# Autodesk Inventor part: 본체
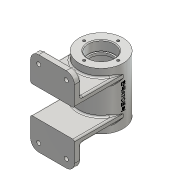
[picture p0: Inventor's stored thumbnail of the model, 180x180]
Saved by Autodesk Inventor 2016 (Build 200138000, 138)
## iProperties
Created: 2017-02
Part Number: 본체
Material: 알루미늄 6061
Document SubType Name: Modeling
Designer: H
Density: 2.7 g/cm^3
Appearance: 알루미늄 - 평지
Mass: 354.768 g
Surface Area: 422.772 cm^2
Volume: 131.396 cm^3
Author: H
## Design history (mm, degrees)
sketch "스케치1"
  geometry: L1 (0, 87.092)-(0, -86.113); L2 (0, 35)-(27, 35); L3 (27, 35)-(27, -35); L4 (27, -35)-(0, -35); L5 (39.632, 10)-(-25.443, 10); L6 (20, 10)-(20, 15); L7 (20, 15)-(32, 15); L8 (32, 15)-(32, 10); 1 further point
  constraints: 16 end point, 5 point on line, 3 perpendicular, 3 vertical, 2 horizontal
  dimensions: "d0" = 35 distance from line of point (0, 0) L2; "d1" = 70 distance of L2.end L3.end; "d2" = 54 diameter of L3 L1; "d3" = 50 diameter of L2 L5; "d4" = 5 distance between parallel lines of L3 L8; "d5" = 10 diameter of L7 L5; "d6" = 20 distance from line of point (0, 0) L6
revolve "회전1" stored, may be unused: angle "d7" = 90 deg
revolve "회전2" stored, may be unused: angle "d8" = 90 deg
sketch "스케치2"
  geometry: L1 (0, 0)-(-19.725, -30.374); L2 (0, 0)-(0, -31.728); L3 (0, 0)-(10.45, -6.786); L4 (-8.17, -12.58)-(-3.138, -15.848); L5 (-3.138, -15.848)-(-11.307, -28.428); L6 (-11.307, -28.428)-(-16.339, -25.16)
  constraints: 12 end point, 2 perpendicular, 2 point on line, 1 parallel, 1 vertical
  dimensions: "d12" = 12 diameter of L5 L1; "d13" = 30 distance between parallel lines of L3 L6; "d14" = 15 distance of L4.end L5.end; "d16" = 33 deg angle of L1 L2
revolve "회전3" sketch "스케치2" stored, may be unused: angle "d15" = 90 deg
sketch "스케치8"
  geometry: L1 (0, 17)-(-60, 17); L2 (-60, 17)-(-60, 52); L3 (0, 25)-(-52, 25); L4 (-52, 25)-(-52, 52); L5 (-60, 52)-(-52, 52); L6 (0, 25)-(0, 17); 1 further point
  constraints: 12 end point, 2 horizontal, 2 perpendicular, 1 vertical
  dimensions: "d52" = 60 distance from line of L2 point (0, 0); "d53" = 8 distance between parallel lines of L1 L3; "d54" = 17 distance from line of point (0, 0) L1; "d55" = 52 vertical distance of L2.end point (0, 0); "d56" = 8 distance of L2.end L4.end; "d57" = 60 distance of L1.start L1.end
extrude "돌출1" join sketch "스케치8" stored distance "d58" = 54; taper "d59" = 0 deg
sketch "스케치3"
  geometry: L1 (0, 45.932)-(0, -47.203); L2 (16, 35)-(16, 23); L3 (16, 23)-(14, 23); L4 (14, 23)-(14, 20); L5 (14, 20)-(22, 20); L6 (22, 20)-(22, -20); L7 (22, -20)-(14, -20); L8 (14, -20)-(14, -23); L9 (14, -23)-(16, -23); L10 (16, -23)-(16, -35); L11 (-27, 35)-(27, 35) reference; L12 (-27, -35)-(27, -35) reference; L13 (16, 35)-(0, 35); L14 (16, -35)-(0, -35); L15 (0, 35)-(0, -35); 1 further point
  constraints: 26 end point, 6 perpendicular, 6 point on line, 2 midpoint, 2 vertical, 1 collinear
  dimensions: "d17" = 44 diameter of L6 L1; "d18" = 12 distance of L2.start L2.end; "d19" = 3 distance of L3.end L4.end; "d20" = 32 diameter of L2 L1; "d21" = 28 diameter of L4 L1; "d22" = 40 distance of L5.end L6.end; "d23" = 12 distance of L9.end L10.end; "d24" = 3 distance of L7.end L8.end
revolve "회전4" sketch "스케치3" stored, may be unused: angle "d25" = 0 deg
sketch "스케치4"
  geometry: C1 r 5 at (0, 0) reference; 2 further points
  constraints: 1 coincident
hole "구멍1" sketch "스케치4" at (0, 0) diameter "d26" = 5.188; stored, may be unused: countersink angle "d30" = 90 deg, drill point angle "d32" = 118 deg; dims "d27" = 12, "d28" = 4, "d29" = 2, "d31" = 16
sketch "스케치5"
  geometry: 2 further points
  constraints: 1 coincident
hole "구멍2" sketch "스케치5" at (0, 0) diameter "d33" = 5.188; stored, may be unused: countersink angle "d37" = 90 deg, drill point angle "d39" = 118 deg; dims "d34" = 12, "d35" = 4, "d36" = 2, "d38" = 16
sketch "스케치6"
  geometry: 2 further points
  dimensions: "d40" = 21 distance of point (0, 0) point (0, 21); "d41" = 0 horizontal distance of point (0, 0) point (0, 21)
hole "구멍3" sketch "스케치6" at (0, 21) diameter "d42" = 3.242; stored, may be unused: countersink angle "d46" = 90 deg, drill point angle "d48" = 118 deg; dims "d43" = 8, "d44" = 4, "d45" = 2, "d47" = 10
fillet "모깎기1" dims "d60" = 10
sketch "스케치9"
  geometry: L1 (5.5, 19.598)-(10, 22.196); L2 (10, 22.196)-(14.5, 19.598); L3 (14.5, 19.598)-(14.5, 14.402); L4 (14.5, 14.402)-(10, 11.804); L5 (10, 11.804)-(5.5, 14.402); L6 (5.5, 14.402)-(5.5, 19.598); L7 (0, -8)-(0, 17) reference; L8 (10, 27)-(44, 27) reference; C1 r 4.5 at (10, 17); 2 further points
  constraints: 12 end point, 1 centre point, 1 coincident, 1 parallel, 1 tangent, 13 other
  dimensions: "d61" = 9 diameter of C1; "d62" = 10 distance from line of L7 point (10, 17); "d63" = 10 distance from line of L8 point (10, 17)
extrude "돌출2" cut sketch "스케치9" distance "d64" = 3; taper "d65" = 0 deg
sketch "스케치10"
  geometry: L1 (10, 27)-(44, 27) reference; L2 (0, -8)-(0, 17) reference; 2 further points
  dimensions: "d66" = 10 distance from line of L1 point (10, 17); "d67" = 10 distance from line of L2 point (10, 17)
hole "구멍4" sketch "스케치10" at (10, 17) diameter "d68" = 5; stored, may be unused: countersink angle "d72" = 90 deg, drill point angle "d74" = 118 deg; dims "d69" = 8, "d70" = 4, "d71" = 2, "d73" = 10
fillet "모깎기2" dims "d75" = 3
fillet "모깎기3" dims "d76" = 0.3
chamfer "모따기1" distance "d77" = 1; stored, may be unused: second distance "d78" = 2, angle "d79" = 45 deg
fillet "모깎기4" dims "d80" = 2, "d81" = 2
fillet "모깎기5" dims "d82" = 2
node "작업 평면1"
sketch "스케치11"
  geometry: L1 (-27, 35)-(27, 35) reference; L2 (27, 35)-(27, -35) reference; 2 further points
  constraints: 1 other
  dimensions: "d84" = 35 distance from line of L1 point (0, 0); "d85" = 27 distance from line of point (0, 0) L2
feature "엠보싱1" sketch "스케치11" dims "d0" = 35, "d1" = 70, "d2" = 54, "d3" = 50, "d4" = 5, "d5" = 10, "d6" = 20, "d12" = 12, "d13" = 30, "d14" = 15, "d16" = 33 deg, "d86" = 0.5, "d87" = 0
node "솔리드1"
mirror "대칭2"
pattern_circular "원형 패턴1" dims angle "d50" = 360 deg
mirror "대칭1"
mirror "대칭3"
mirror "대칭4"
